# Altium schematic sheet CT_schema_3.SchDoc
size 298 x 247 mm
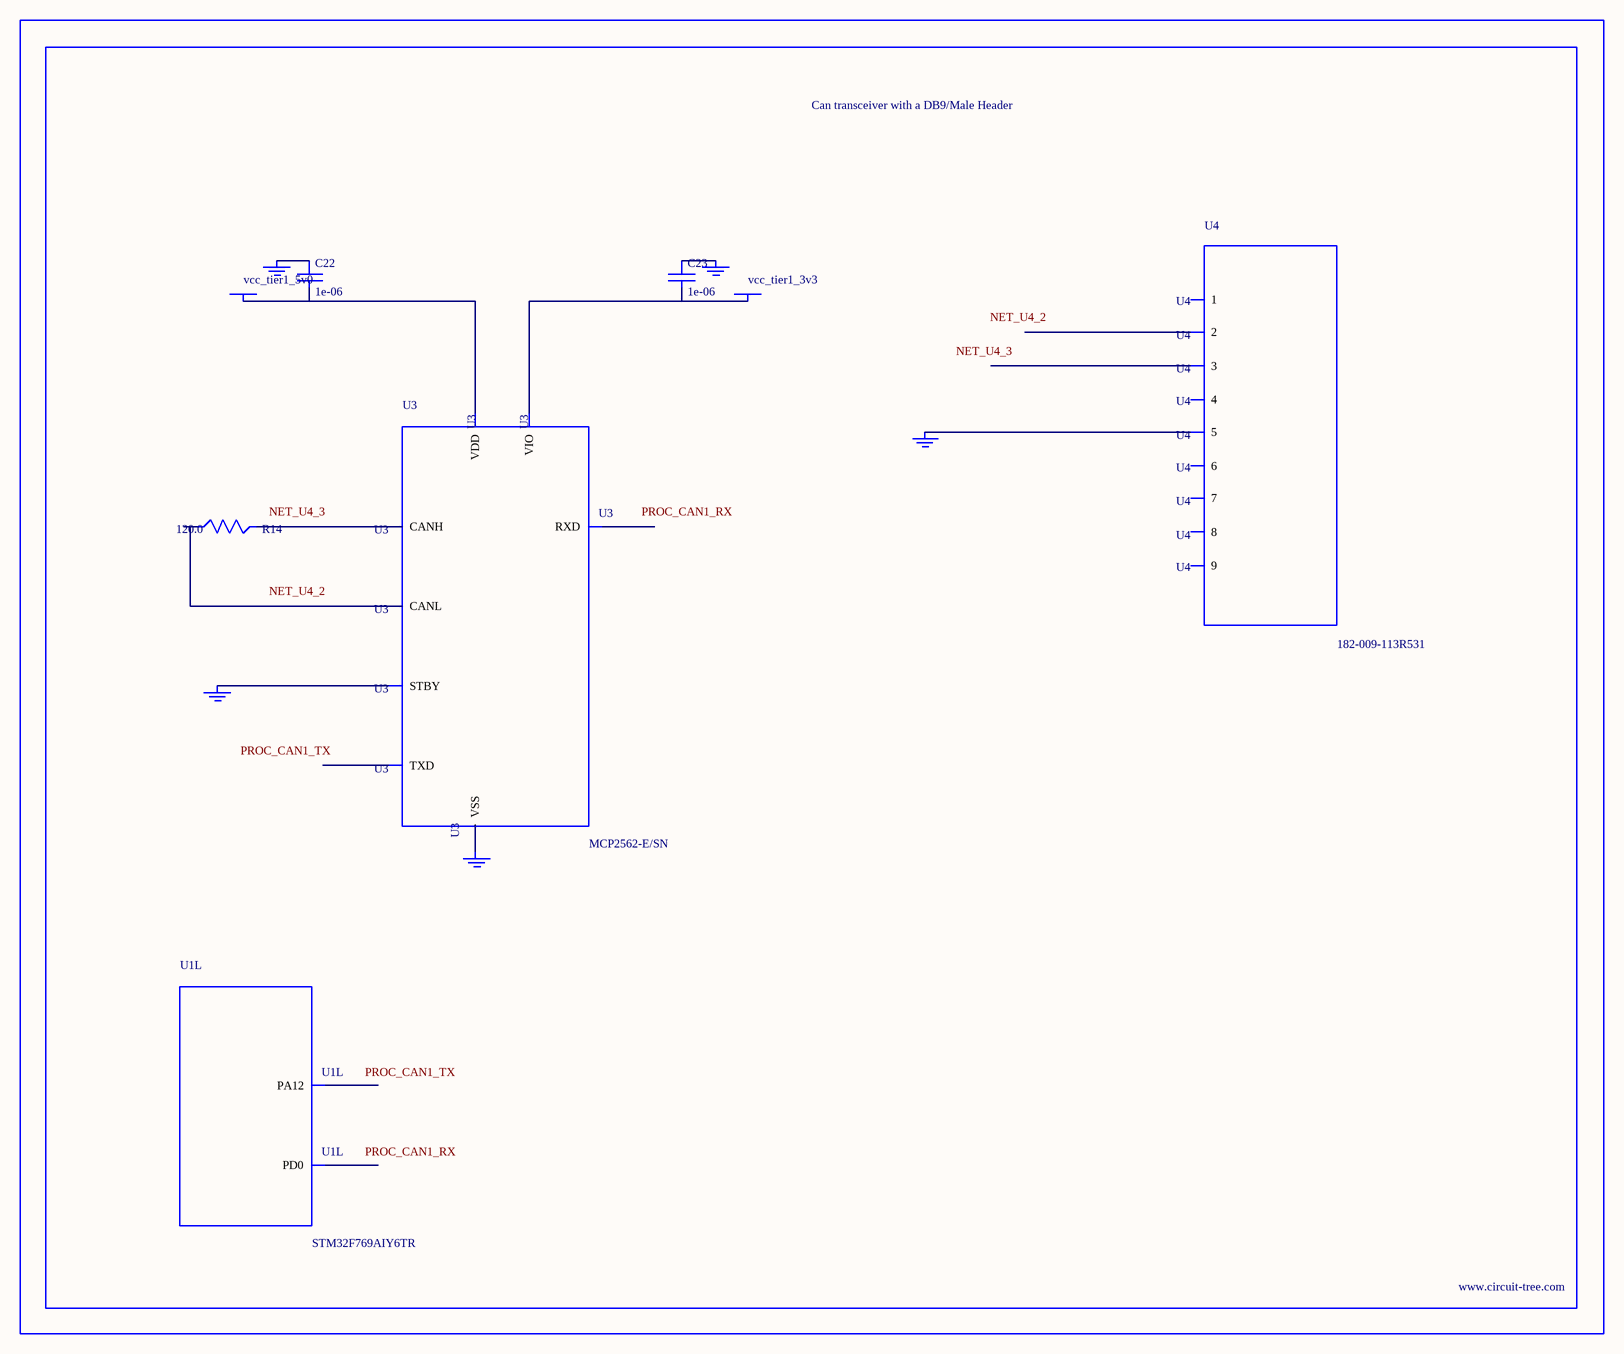
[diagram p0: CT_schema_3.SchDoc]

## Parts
BORDER2  (no value)
C22  1e-06  [C0603]
C23  1e-06  [C0603]
GND_INSTANCE_2_0  (no value)
GND_INSTANCE_2_1  (no value)
GND_INSTANCE_2_2  (no value)
GND_INSTANCE_2_3  (no value)
GND_INSTANCE_2_4  (no value)
POWER_INSTANCE_2_0  vcc_tier1_5v0
POWER_INSTANCE_2_1  vcc_tier1_3v3
R14  120.0  [R0603]
U1  STM32F769AIY6TR  [WLCSP180]  (part L of 15)
U3  MCP2562-E/SN  [SOIC-8]
U4  182-009-113R531  [182-009-MALE]

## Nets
NetC22_1: C22.1 GND_INSTANCE_2_0.0(GND)
NetC22_2: C22.2 POWER_INSTANCE_2_0.0(PWR) U3.3(VDD)
NetC23_1: C23.1 GND_INSTANCE_2_1.0(GND)
NetC23_2: C23.2 POWER_INSTANCE_2_1.0(PWR) U3.5(VIO)
NetGND_INSTANCE_2_2_0: GND_INSTANCE_2_2.0(GND) U3.8(STBY)
NetGND_INSTANCE_2_3_0: GND_INSTANCE_2_3.0(GND) U3.2(VSS)
NetGND_INSTANCE_2_4_0: GND_INSTANCE_2_4.0(GND) U4.5
NetR14_1: R14.1 U3.6(CANL)
NetR14_2: R14.2 U3.7(CANH)

Not connected (* = marked no-connect by the designer): U1 A4(PD0) D1(PA12); U3 1(TXD) 4(RXD); U4 1 2 3 4 6 7 8 9

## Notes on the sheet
- Labels drawn without touching a wire or pin: NET_U4_2, NET_U4_3, PROC_CAN1_RX, PROC_CAN1_TX

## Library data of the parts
BORDER2 = BORDER_PAGE2
C22 C23 = C0603C105K3RACTU
GND_INSTANCE_2_0-GND_INSTANCE_2_4 = GND
POWER_INSTANCE_2_0 POWER_INSTANCE_2_1 = PWR
R14 = RC0603JR-07120RL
